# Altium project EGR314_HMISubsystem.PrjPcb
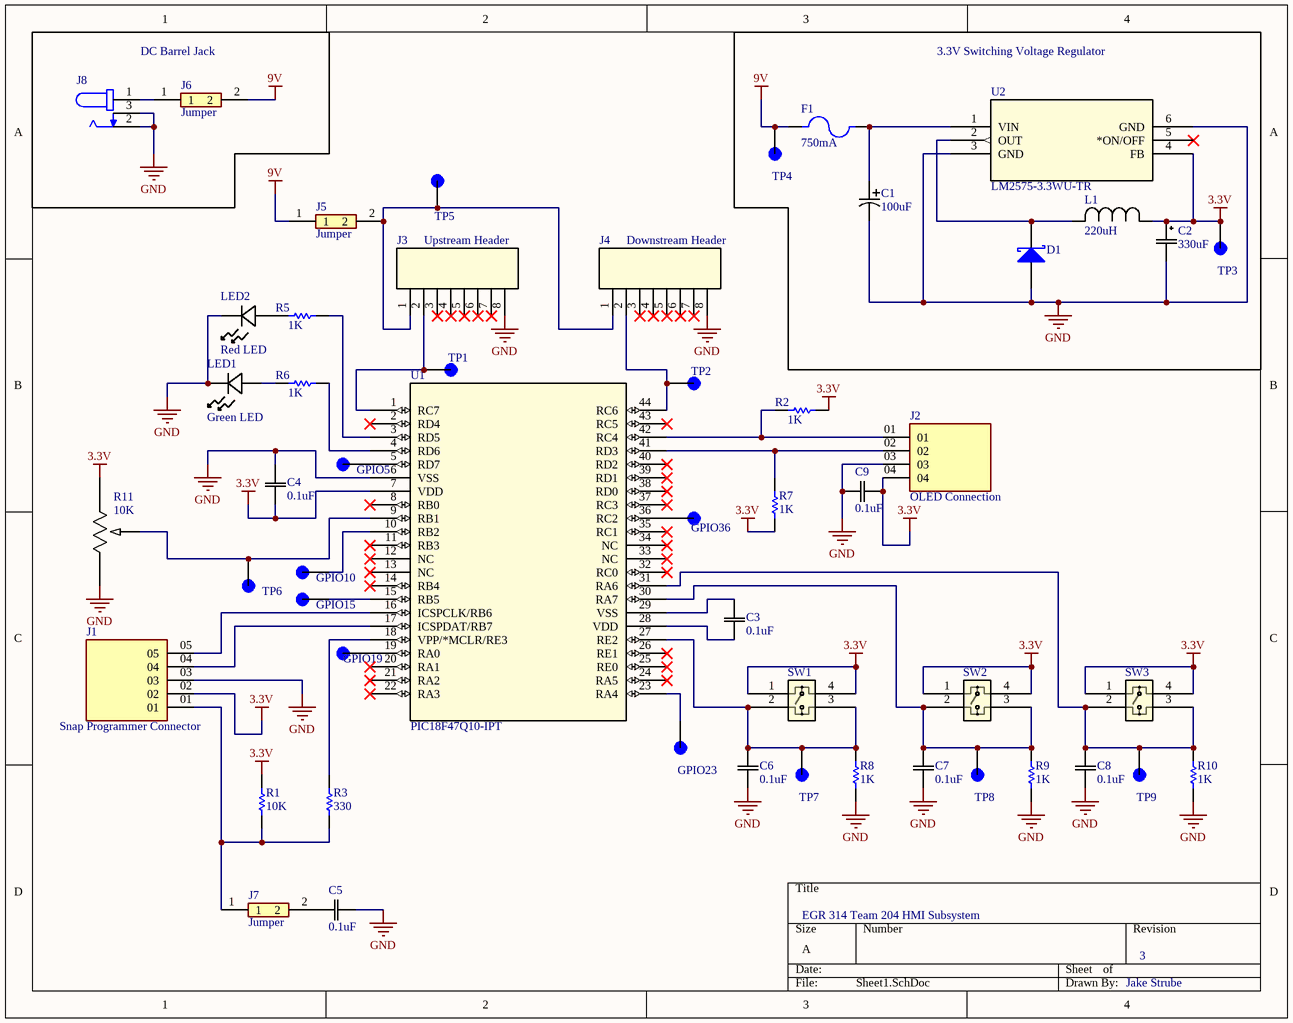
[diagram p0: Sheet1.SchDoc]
1 sheet, 52 parts. Net scope: global (net labels, ports and power ports of the same name join across sheets).
Board file: PCB1.PcbDoc

## Sheet Sheet1.SchDoc
size A; SheetNumber: 1; SheetTotal: 1

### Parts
C1  100uF  [CAP_PAN_EEE_F_PAN]
C2  330uF  [CAP_UCD_10X10_NCH]
C3  0.1uF  [CAP_UWF_4X5P4_NCH]
C4  0.1uF  [CAP_UWF_4X5P4_NCH]
C5  0.1uF  [CAP_UWF_4X5P4_NCH]
C6  0.1uF  [CAP_UWF_4X5P4_NCH]
C7  0.1uF  [CAP_UWF_4X5P4_NCH]
C8  0.1uF  [CAP_UWF_4X5P4_NCH]
C9  0.1uF  [CAP_UWF_4X5P4_NCH]
D1  Schottky Diode  (value not drawn)
F1  750mA  [FUSE_4628]
GPIO5  5277  [KEYSTONE_5277]  (value not drawn)
GPIO10  5277  [KEYSTONE_5277]  (value not drawn)
GPIO15  5277  [KEYSTONE_5277]  (value not drawn)
GPIO19  5277  [KEYSTONE_5277]  (value not drawn)
GPIO23  5277  [KEYSTONE_5277]  (value not drawn)
GPIO36  5277  [KEYSTONE_5277]  (value not drawn)
J1  Snap Programmer Connector  [SAMTEC_MTSW-105-07-G-S-229]
J2  OLED Connection  [SAMTEC_TSW-104-08-L-S-LL]
J3  Upstream Header  [CONN_2PH2-08-UA_ADM]
J4  Downstream Header  [CONN_2PH2-08-UA_ADM]
J5  Jumper  [SAMTEC_MTSW-101-X-X-D-X]
J6  Jumper  [SAMTEC_MTSW-101-X-X-D-X]
J7  Jumper  [SAMTEC_MTSW-101-X-X-D-X]
J8  DCJ200-10-A-XX-K_REVA  [GCT_DCJ200-10-A-XX-K_REVA]  (value not drawn)
L1  220uH  [IND_12565_TDK]
LED1  Green LED  [LED_LTST-C190CKT_LTO]
LED2  Red LED  [LED_LTST-C190_LTO]
R1  10K  [RESC1005X40X25LL05T10]
R2  1K  [RESC1005X40X25LL05T10]
R3  330  [RESC1608X55X25LL10T15]
R5  1K  [RESC1005X40X25LL05T10]
R6  1K  [RESC1005X40X25LL05T10]
R7  1K  [RESC1005X40X25LL05T10]
R8  1K  [RESC1005X40X25LL05T10]
R9  1K  [RESC1005X40X25LL05T10]
R10  1K  [RESC1005X40X25LL05T10]
R11  10K  [POT_RK09K113004U_AAL]
SW1  COM-10302  [COM-10302_SPK]  (value not drawn)
SW2  COM-10302  [COM-10302_SPK]  (value not drawn)
SW3  COM-10302  [COM-10302_SPK]  (value not drawn)
TP1  5277  [KEYSTONE_5277]  (value not drawn)
TP2  5277  [KEYSTONE_5277]  (value not drawn)
TP3  5277  [KEYSTONE_5277]  (value not drawn)
TP4  5277  [KEYSTONE_5277]  (value not drawn)
TP5  5277  [KEYSTONE_5277]  (value not drawn)
TP6  5277  [KEYSTONE_5277]  (value not drawn)
TP7  5277  [KEYSTONE_5277]  (value not drawn)
TP8  5277  [KEYSTONE_5277]  (value not drawn)
TP9  5277  [KEYSTONE_5277]  (value not drawn)
U1  PIC18F47Q10-IPT  [TQFP44_PT_MCH]
U2  LM2575-3.3WU-TR  [TO-263-5T_MCH-L]

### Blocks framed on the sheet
DC Barrel Jack: J6 J8
3.3V Switching Voltage Regulator: C1 C2 D1 F1 L1 TP3 TP4 U2

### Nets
3.3V: C2.1 C4.1 C9.2 J1.02 J2.04 L1.1 R1.1 R2.1 R7.2 R11.1 SW1.1 SW1.4 SW2.1 SW2.4 SW3.1 SW3.4 TP3.1(TP) U1.7(VDD) U2.4(FB)
9V: F1.1 J5.1 J6.2 TP4.1(TP)
GND: C1.2 C2.2 C4.2 C5.1 C6.2 C7.2 C8.2 C9.1 D1.1(A) J1.03 J2.03 J3.8 J4.8 J8.2 J8.3 LED1.1 LED2.1(CATHODE) R8.1 R9.1 R10.1 R11.3 U1.6(VSS) U2.3(GND) U2.6(GND)
NetC1_1: C1.1 F1.2 U2.1(VIN)
NetC3_1: C3.1 U1.28(VDD)
NetC3_2: C3.2 U1.29(VSS)
NetC5_2: C5.2 J7.2
NetC6_1: C6.1 R8.2 SW1.2 SW1.3 TP7.1(TP) U1.27(RE2)
NetC7_1: C7.1 R9.2 SW2.2 SW2.3 TP8.1(TP) U1.30(RA7)
NetC8_1: C8.1 R10.2 SW3.2 SW3.3 TP9.1(TP) U1.31(RA6)
NetD1_2: D1.2(K) L1.2 U2.2(OUT)
NetGPIO5_1: GPIO5.1(TP) U1.5(RD7)
NetGPIO10_1: GPIO10.1(TP) U1.10(RB2)
NetGPIO15_1: GPIO15.1(TP) U1.15(RB5)
NetGPIO19_1: GPIO19.1(TP) U1.19(RA0)
NetGPIO23_1: GPIO23.1(TP) U1.23(RA4)
NetGPIO36_1: GPIO36.1(TP) U1.36(RC2)
NetJ1_01: J1.01 J7.1 R1.2 R3.1
NetJ1_04: J1.04 U1.17(ICSPDAT/RB7)
NetJ1_05: J1.05 U1.16(ICSPCLK/RB6)
NetJ2_01: J2.01 R2.2 U1.42(RC4)
NetJ2_02: J2.02 R7.1 U1.41(RD3)
NetJ3_1: J3.1 J4.1 J5.2 TP5.1(TP)
NetJ3_2: J3.2 TP1.1(TP) U1.1(RC7)
NetJ4_2: J4.2 TP2.1(TP) U1.44(RC6)
NetJ6_1: J6.1 J8.1
NetLED1_2: LED1.2 R6.1
NetLED2_2: LED2.2(ANODE) R5.1
NetR3_2: R3.2 U1.18(VPP/*MCLR/RE3)
NetR5_2: R5.2 U1.3(RD5)
NetR6_2: R6.2 U1.4(RD6)
NetR11_2: R11.2 TP6.1(TP) U1.9(RB1)

Not connected (* = marked no-connect by the designer): J3 3* 4* 5* 6* 7*; J4 3* 4* 5* 6* 7*; U1 2(RD4)* 8(RB0)* 11(RB3)* 12(NC)* 13(NC)* 14(RB4)* 20(RA1)* 21(RA2)* 22(RA3)* 24(RA5)* 25(RE0)* 26(RE1)* 32(RC0)* 33(NC)* 34(NC)* 35(RC1)* 37(RC3)* 38(RD0)* 39(RD1)* 40(RD2)* 43(RC5)*; U2 5(*ON/OFF)*

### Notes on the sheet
- EGR 314 Team 204 HMI Subsystem
- 3
- Jake Strube

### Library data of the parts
C1 = EEE-1HA101UAP: No Description Available; Mfr_Name: Panasonic
C2 = UCM1H331MNL1GS: No Description Available; Mfr_Name: Nichicon
C3-C9 = UWP1H0R1MCL1GB: No Description Available; Mfr_Name: Nichicon
D1 = Schottky Diode: AF: 1; BV: 0; BV_MAX: 1e99; EG: 1.11; FC: 0.5; IBV: 0.001; IS: 1e-14; MJSW: 0.33; NTUN: 30; TNOM: 27; XTI: 3; SimulationGenericComponent: True
F1 = 4628: 5mm Slim Line Fuse holder; MF: Keystone
GPIO5 GPIO10 GPIO15 GPIO19 GPIO23 GPIO36 TP1-TP9 = 5277: TEST POINT (BLUE) - COMPACT; MF: Keystone Electronics
J1 = MTSW-105-07-G-S-229
J2 = TSW-104-08-L-S-LL
J3 J4 = 2PH2-08-UA: No Description Available; Mfr_Name: ADAM TECHNOLOGIES INC
J5-J7 = MTSW-101-X-X-D-X: Variable Height PCB Header Strips, 0.100 pitch; MF: SAMTEC; MP: MTSW-101-09-L-D-210
J8 = DCJ200-10-A-XX-K_REVA: Power Barrel Connector Jack 2.05mm ID (0.081), 5.50mm OD (0.217) Through Hole, Right Angle; MF: Global Connector Technology; MP: DCJ200-10-A-K1-K
L1 = SLF12565T-221M1R0-H: No Description Available; Mfr_Name: TDK
LED1 = LTST-C190GKT: No Description Available; Mfr_Name: LITE-ON
LED2 = LTST-C190KRKT: No Description Available; Mfr_Name: LITE-ON; Type: LED Indication
R1 R2 R5-R10 = CMP-2002-07941-1: Part Number: RC0402JR-071KL; Manufacturer: Yageo / Phycomp
R3 = CMP-2000-06958-1: Chip Resistor, 330 Ohm, +/- 5%, 50 V, -55 to 155 degC, 0603 (1608 Metric), -40 to 155 degC, RoHS, Tape and Reel; Manufacturer: Yageo; Temperature Coefficient: ±100ppm/°C; Power Rating: 100mW; Voltage Rating: 50V; Product Range: RCSeries; SVHC: ToBeAdvised; Resistance: 330ohm; Resistor Element Type: ThickFilm; Resistor Case Style: 0603[1608Metric]
R11 = RK09K113004U: No Description Available; Mfr_Name: Alps Electric
SW1-SW3 = COM-10302: No Description Available; Mfr_Name: Sparkfun
U1 = PIC18F47Q10-IPT: No Description Available; Mfr_Name: Microchip
U2 = LM2575-3.3WU-TR: No Description Available; Mfr_Name: Microchip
